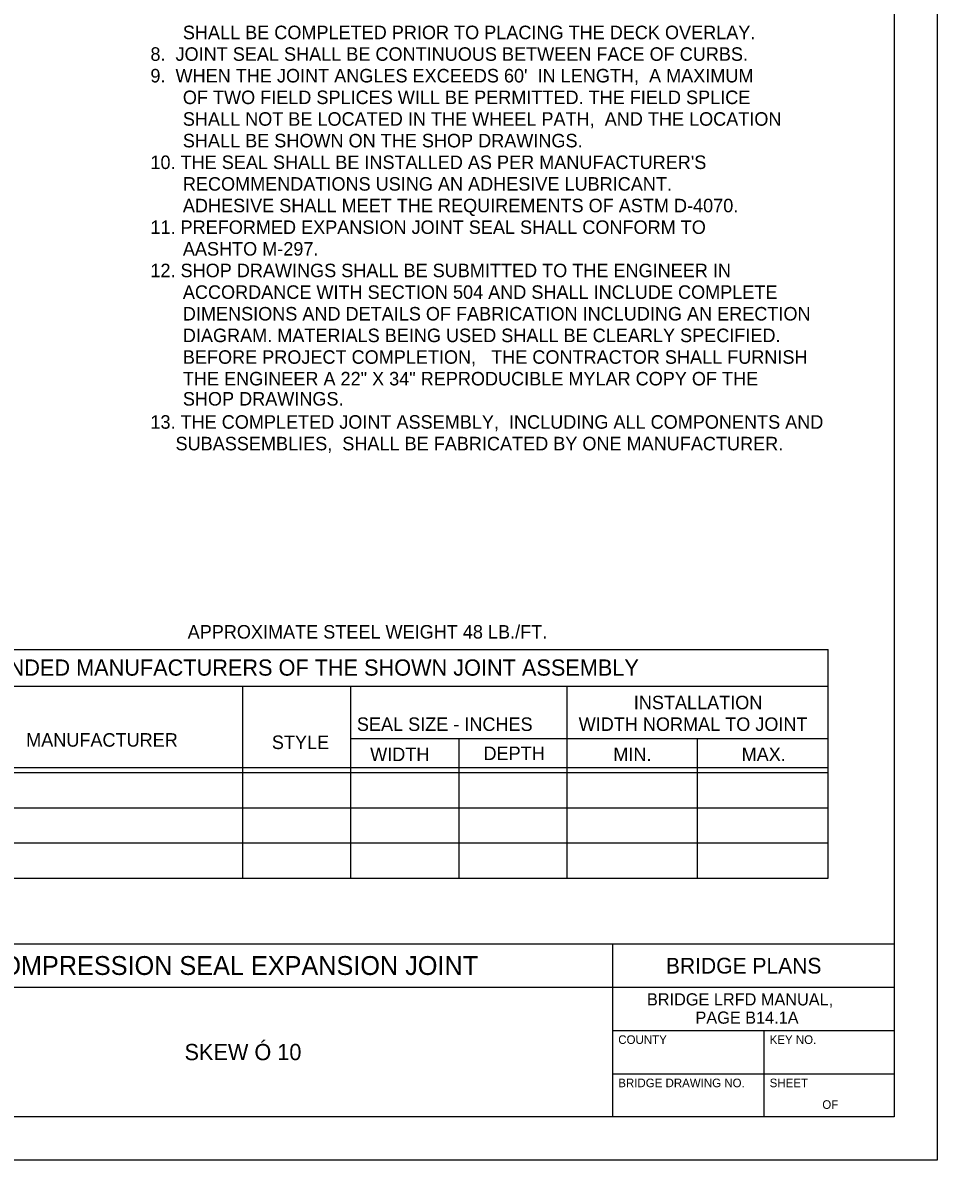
# Model space of a CAD drawing. Extents: x 0 to 11.3, y 0 to 7.9.
# Drawn here: x 7.81 to 11.333, y 0 to 4.38 of the extents above; entities that cross this region are included whole.
import ezdxf

# ---------------------------------------------------------------- set-up
doc = ezdxf.new("R2010")
doc.units = 0
for name, color, linetype in [('BORDER_ANNO_Cutsheet', 7, 'Continuous'), ('BRDG_ANNO_Anno-Sheet', 7, 'Continuous'), ('BRDG_ANNO_General-Notes', 7, 'Continuous')]:
    doc.layers.add(name, color=color, linetype=linetype)

msp = doc.modelspace()

# ---------------------------------------------------------------- linework, layer by layer
at = {"layer": 'BORDER_ANNO_Cutsheet'}
msp.add_lwpolyline([(0, 7.3333), (11.3333, 7.3333), (11.3333, 0), (0, 0)], close=True, dxfattribs=at)
at = {"layer": 'BRDG_ANNO_Anno-Sheet'}
for p, q in [((6.4167, 0.8333), (11.1667, 0.8333)), ((10.0833, 0.1667), (10.0833, 0.8333)), ((7.4167, 0.6667), (10.0833, 0.6667)), ((10.0833, 0.6667), (11.1667, 0.6667)), ((10.0833, 0.5), (11.1667, 0.5)), ((10.6667, 0.1667), (10.6667, 0.5)), ((10.0833, 0.3333), (11.1667, 0.3333))]:
    msp.add_line(p, q, dxfattribs=at)
msp.add_lwpolyline([(0.5, 7.1667), (11.1667, 7.1667), (11.1667, 0.1667), (0.5, 0.1667)], close=True, dxfattribs=at)
at = {"layer": 'BRDG_ANNO_General-Notes'}
for p, q in [((6.7408, 1.9669), (10.9133, 1.9669)), ((10.9132, 1.0856), (10.9132, 1.9669)), ((10.9133, 1.8245), (6.7408, 1.8245)), ((8.6574, 1.0856), (8.6574, 1.8245)), ((9.0741, 1.0856), (9.0741, 1.8245)), ((9.9072, 1.0856), (9.9072, 1.8245)), ((10.9133, 1.6227), (9.0741, 1.6227)), ((9.4906, 1.0856), (9.4906, 1.6227)), ((10.4095, 1.0856), (10.4095, 1.6227)), ((6.7408, 1.5129), (10.9133, 1.5129)), ((10.9133, 1.4921), (6.7408, 1.4921)), ((6.7408, 1.3565), (10.9133, 1.3565)), ((10.9133, 1.221), (6.7408, 1.221)), ((6.7408, 1.0856), (10.9133, 1.0856))]:
    msp.add_line(p, q, dxfattribs=at)

# ---------------------------------------------------------------- texts
at = {"layer": 'BRDG_ANNO_Anno-Sheet'}
for s, height, p in [('COMPRESSION SEAL EXPANSION JOINT', 0.072709, (7.6569, 0.7135)), ('BRIDGE PLANS', 0.060625, (10.2878, 0.7188)), ('BRIDGE LRFD MANUAL,', 0.046875, (10.2148, 0.5961)), ('PAGE B14.1A', 0.046875, (10.4017, 0.5258)), ('SKEW Ó 10', 0.0625, (8.4328, 0.3854)), ('COUNTY', 0.03313, (10.1042, 0.4479)), ('KEY NO.', 0.03313, (10.6875, 0.4479)), ('BRIDGE DRAWING NO.', 0.033125, (10.1042, 0.2812)), ('SHEET', 0.03313, (10.6875, 0.2812)), ('OF', 0.03313, (10.8904, 0.1979))]:
    msp.add_text(s, height=height, dxfattribs=at).set_placement(p)
at = {"layer": 'BRDG_ANNO_General-Notes'}
for s, height, p in [('SHALL BE COMPLETED PRIOR TO PLACING THE DECK OVERLAY.', 0.052083, (8.4265, 4.3169)), ('8.  JOINT SEAL SHALL BE CONTINUOUS BETWEEN FACE OF CURBS.', 0.052083, (8.3015, 4.2336)), ("9.  WHEN THE JOINT ANGLES EXCEEDS 60'  IN LENGTH,  A MAXIMUM ", 0.052083, (8.3015, 4.1503)), ('OF TWO FIELD SPLICES WILL BE PERMITTED. THE FIELD SPLICE', 0.052083, (8.4265, 4.0669)), ('SHALL NOT BE LOCATED IN THE WHEEL PATH,  AND THE LOCATION', 0.052083, (8.4265, 3.9836)), ('SHALL BE SHOWN ON THE SHOP DRAWINGS.', 0.052083, (8.4265, 3.9003)), ("10. THE SEAL SHALL BE INSTALLED AS PER MANUFACTURER'S", 0.052083, (8.3015, 3.8169)), ('RECOMMENDATIONS USING AN ADHESIVE LUBRICANT.', 0.052083, (8.4265, 3.7336)), ('ADHESIVE SHALL MEET THE REQUIREMENTS OF ASTM D-4070.', 0.052083, (8.4265, 3.6503)), ('11. PREFORMED EXPANSION JOINT SEAL SHALL CONFORM TO ', 0.052083, (8.3015, 3.5669)), ('AASHTO M-297.', 0.052083, (8.4265, 3.4836)), ('12. SHOP DRAWINGS SHALL BE SUBMITTED TO THE ENGINEER IN ', 0.052083, (8.3015, 3.4003)), ('ACCORDANCE WITH SECTION 504 AND SHALL INCLUDE COMPLETE ', 0.052083, (8.4265, 3.3169)), ('DIMENSIONS AND DETAILS OF FABRICATION INCLUDING AN ERECTION ', 0.052083, (8.4265, 3.2336)), ('DIAGRAM. MATERIALS BEING USED SHALL BE CLEARLY SPECIFIED. ', 0.052083, (8.4265, 3.1503)), ('BEFORE PROJECT COMPLETION,   THE CONTRACTOR SHALL FURNISH', 0.052083, (8.4265, 3.0669)), ('THE ENGINEER A 22" X 34" REPRODUCIBLE MYLAR COPY OF THE', 0.052083, (8.4265, 2.9836)), ('SHOP DRAWINGS.', 0.052083, (8.4265, 2.9061)), ('13. THE COMPLETED JOINT ASSEMBLY,  INCLUDING ALL COMPONENTS AND', 0.052083, (8.3015, 2.8169)), (' SUBASSEMBLIES,  SHALL BE FABRICATED BY ONE MANUFACTURER.', 0.052083, (8.379, 2.7336)), ('APPROXIMATE STEEL WEIGHT 48 LB./FT.', 0.052083, (8.445, 2.0088)), ('RECOMMENDED MANUFACTURERS OF THE SHOWN JOINT ASSEMBLY', 0.0625, (7.3186, 1.866)), ('INSTALLATION', 0.052057, (10.1641, 1.7365)), ('SEAL SIZE - INCHES', 0.052083, (9.097, 1.6531)), ('WIDTH NORMAL TO JOINT', 0.052057, (9.9516, 1.6532)), ('MANUFACTURER', 0.052083, (7.8227, 1.5925)), ('STYLE', 0.05208, (8.7695, 1.5834)), ('WIDTH', 0.05208, (9.1482, 1.5371)), ('DEPTH', 0.05208, (9.5849, 1.5409)), ('MIN.', 0.05208, (10.0852, 1.5371)), ('MAX.', 0.05208, (10.5795, 1.5371))]:
    msp.add_text(s, height=height, dxfattribs=at).set_placement(p)

doc.saveas('drawing.dxf')
